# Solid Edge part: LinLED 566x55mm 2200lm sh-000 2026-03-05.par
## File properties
Author: robert.pupel
Template: iso metric part.par
Last saved by: robert.pupel
Revision: 2
Application: Solid Edge
Gęstość: 0.000 kg/m^3
Dokładność: 0.990
Username: robert.pupel
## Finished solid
Body 1: solid body, 2024 faces, 5270 edges, 3418 vertices.
  Faces by surface: plane 1480, cylinder 286, torus 104, cone 88, spline 46, sphere 20
  Edges by curve: line 3968, curve on surface 686, circle 326, spline 158, ellipse 132
Bounding box of the edges (mm; curved faces can reach further): 565.600 x 5.050 x 55.000, from (-282.8, -3.45, -27.5) to (282.8, 1.6, 27.5).
Cylindrical faces by radius (mm): R0.199 x2, R0.2 x78, R0.2002 x4, R0.2169 x6, R0.25 x24, R0.3 x4, R0.3373 x6, R0.4 x16, R0.4006 x4, R0.4008 x4, R0.5 x8, R0.525 x4, R0.6 x24, R0.75 x16, R1 x14, R1.0894 x4, R1.0991 x8, R1.1 x28, R1.5309 x2, R1.531 x2, R1.5312 x2, R1.5314 x2, R1.7406 x2, R1.7414 x2, R1.7416 x2, R1.7423 x2, R2.375 x16
Conical faces (half-angle, radius in mm at the cone's reference point): 0.3913 deg R1.0968 x4, 0.447 deg R1.0952 x4, 0.464 deg R1.0955 x4, 0.5 deg R0.5056 x8, 0.5 deg R1.0082 x8, 1 deg R0.5511 x4, 10 deg R0.2132 x4, 10 deg R0.4132 x4, 15.6748 deg R1.1041 x2, 15.6751 deg R1.1041 x2, 15.7937 deg R1.1267 x2, 15.7938 deg R1.1267 x2, 18.4844 deg R1.0657 x8, 18.9316 deg R0.5099 x4, 19.4337 deg R0.5111 x4, 27.363 deg R0.6214 x4, 40.1968 deg R0.519 x2, 40.228 deg R0.5176 x2, 42.9179 deg R0.4919 x2, 42.9331 deg R0.4916 x2, 45 deg R0.575 x4, 45 deg R0.625 x8
Toroidal faces (ring radius, tube radius in mm): R0.0958 r0.3997 x8, R0.1 r0.2 x2, R0.1075 r0.4 x4, R0.1101 r0.4001 x4, R0.1216 r0.4 x4, R0.1234 r0.4 x4, R0.1634 r0.2287 x2, R0.1641 r0.2287 x2, R0.3286 r0.2001 x2, R0.3702 r0.4 x4, R0.3818 r0.2 x4, R0.4163 r0.3984 x4, R0.4824 r0.2001 x2, R0.4952 r0.2 x2, R0.6008 r0.3968 x4, R0.6009 r0.3969 x4, R0.6227 r0.2 x2, R0.6235 r0.2 x2, R0.8 r0.2 x8, R0.8522 r0.3 x4, R0.9002 r0.2 x2, R0.9018 r0.2 x2, R0.9181 r0.2227 x4, R0.9197 r0.223 x2, R0.9199 r0.223 x2, R0.9663 r0.2263 x2, R0.9665 r0.2263 x2, R1.3 r0.2 x4, R1.327 r1.1 x4, R1.3271 r1.1 x4, R1.8741 r0.2175 x2, R1.8987 r0.2 x2
Spherical faces by radius (mm): R0.2 x16, R0.6 x4
Planar faces by outward normal: +x 168, +y 15, +z 191, -x 168, -y 249, -z 191, oblique 498
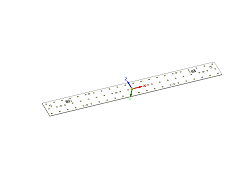
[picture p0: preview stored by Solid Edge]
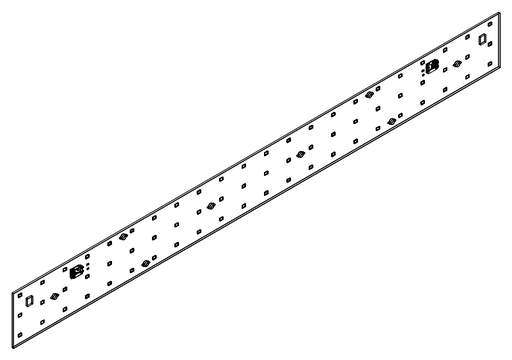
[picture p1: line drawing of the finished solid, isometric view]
